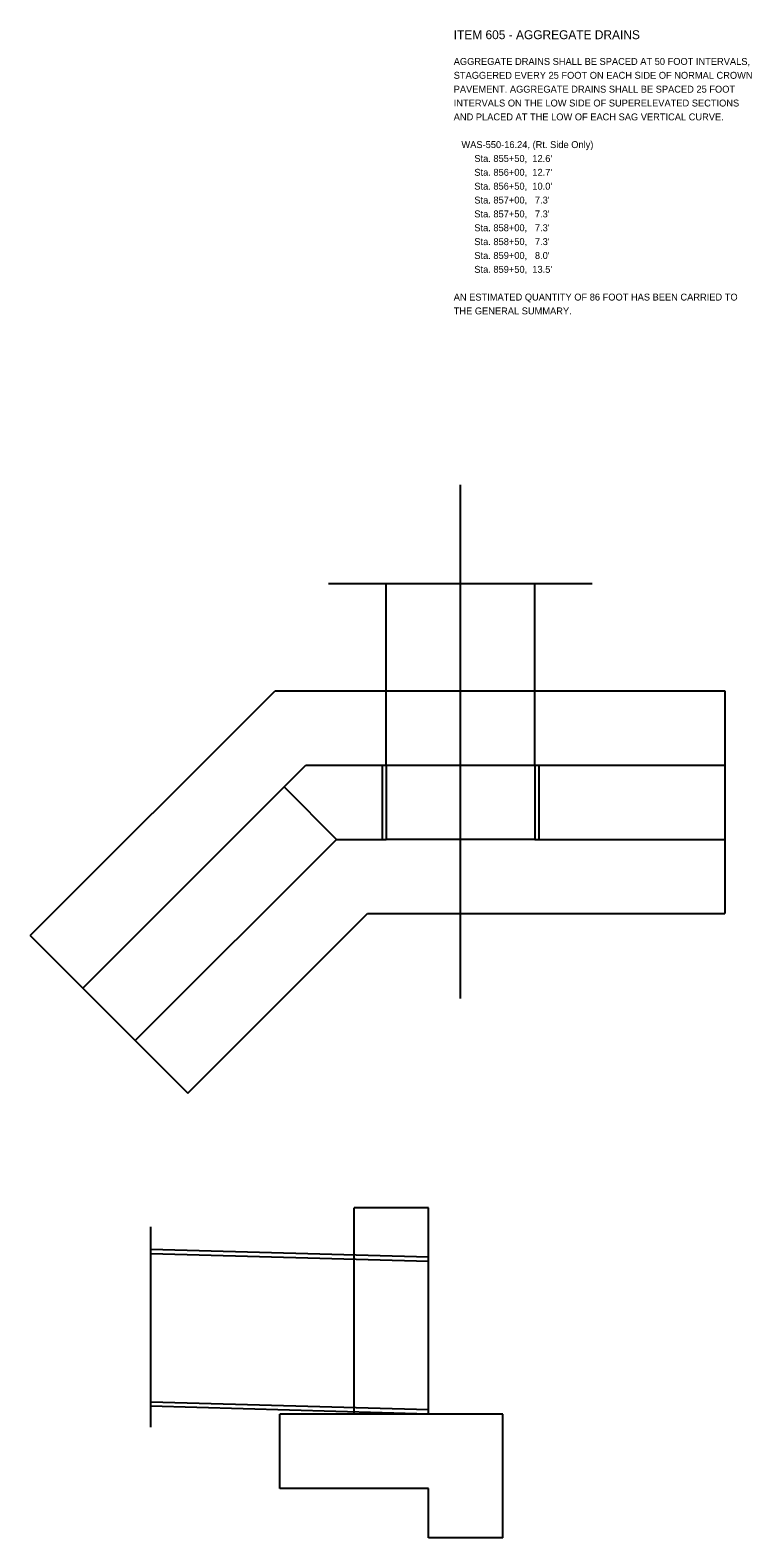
# Model space of a CAD drawing. Extents: x -30 to 76, y -31 to 50.
# Drawn here: x 0.2 to 14.77, y -31.43 to -0.98 of the extents above; entities that cross this region are included whole.
import ezdxf

# ---------------------------------------------------------------- set-up
doc = ezdxf.new("R2010")
doc.units = 0
for name, color, linetype in [('DR_P_Culvert', 7, 'Continuous'), ('DR_P_Headwall', 7, 'Continuous'), ('SH_Text', 7, 'Continuous'), ('XS_P_Headwall', 7, 'Continuous')]:
    doc.layers.add(name, color=color, linetype=linetype)

msp = doc.modelspace()

# ---------------------------------------------------------------- linework, layer by layer
at = {"layer": 'DR_P_Culvert'}
for p, q in [((7.384, -15.824), (7.384, -12.152)), ((10.384, -15.824), (10.384, -12.152)), ((7.301, -15.824), (7.301, -17.324)), ((7.384, -15.824), (7.384, -17.324)), ((10.384, -15.824), (10.384, -17.324)), ((10.467, -15.824), (10.467, -17.324)), ((8.236, -25.851), (2.631, -25.694)), ((8.236, -25.767), (2.633, -25.611)), ((8.236, -28.934), (8.236, -25.767)), ((8.236, -28.934), (2.629, -28.777)), ((8.236, -28.851), (2.631, -28.694))]:
    msp.add_line(p, q, dxfattribs=at)
at = {"layer": 'DR_P_Headwall'}
for p, q in [((0.197, -19.268), (5.141, -14.324)), ((5.141, -14.324), (7.384, -14.324)), ((7.384, -14.324), (10.384, -14.324)), ((10.384, -14.324), (14.217, -14.324)), ((14.217, -14.324), (14.217, -15.824)), ((1.258, -20.329), (5.763, -15.824)), ((5.763, -15.824), (7.384, -15.824)), ((7.384, -15.824), (10.384, -15.824)), ((10.384, -15.824), (14.217, -15.824)), ((14.217, -15.824), (14.217, -17.324)), ((5.323, -16.263), (6.384, -17.324)), ((2.318, -21.389), (6.384, -17.324)), ((6.384, -17.324), (7.384, -17.324)), ((10.384, -17.324), (7.384, -17.324)), ((10.384, -17.324), (14.217, -17.324)), ((14.217, -17.324), (14.217, -18.824)), ((3.379, -22.45), (7.005, -18.824)), ((7.005, -18.824), (14.217, -18.824)), ((0.197, -19.268), (1.258, -20.329)), ((1.258, -20.329), (2.318, -21.389)), ((2.318, -21.389), (3.379, -22.45)), ((8.236, -28.934), (6.736, -28.934))]:
    msp.add_line(p, q, dxfattribs=at)
at = {"layer": 'SH_Text'}
for p, q in [((8.884, -20.538), (8.884, -10.161)), ((6.219, -12.152), (11.54, -12.152))]:
    msp.add_line(p, q, dxfattribs=at)
at = {"layer": 'XS_P_Headwall'}
for p, q in [((6.736, -25.813), (6.736, -24.767)), ((8.236, -24.767), (6.736, -24.767)), ((8.236, -25.767), (8.236, -24.767)), ((2.631, -29.199), (2.631, -25.149)), ((6.736, -28.892), (6.736, -25.813)), ((5.236, -30.434), (5.236, -28.934)), ((6.736, -28.934), (5.236, -28.934)), ((6.736, -28.934), (6.736, -28.892)), ((9.736, -28.934), (8.236, -28.934)), ((9.736, -31.434), (9.736, -28.934)), ((8.236, -30.434), (5.236, -30.434)), ((8.236, -31.434), (8.236, -30.434)), ((9.736, -31.434), (8.236, -31.434))]:
    msp.add_line(p, q, dxfattribs=at)

# ---------------------------------------------------------------- texts
at = {"layer": 'SH_Text'}
for s, height, p in [('ITEM 605 - AGGREGATE DRAINS', 0.18, (8.747, -1.158)), ('AGGREGATE DRAINS SHALL BE SPACED AT 50 FOOT INTERVALS,', 0.14, (8.747, -1.678)), ('STAGGERED EVERY 25 FOOT ON EACH SIDE OF NORMAL CROWN', 0.14, (8.747, -1.958)), ('PAVEMENT. AGGREGATE DRAINS SHALL BE SPACED 25 FOOT', 0.14, (8.747, -2.238)), ('INTERVALS ON THE LOW SIDE OF SUPERELEVATED SECTIONS', 0.14, (8.747, -2.518)), ('AND PLACED AT THE LOW OF EACH SAG VERTICAL CURVE.', 0.14, (8.747, -2.798)), ('   WAS-550-16.24, (Rt. Side Only)', 0.14, (8.747, -3.358)), ("        Sta. 855+50,  12.6'", 0.14, (8.747, -3.638)), ("        Sta. 856+00,  12.7'", 0.14, (8.747, -3.918)), ("        Sta. 856+50,  10.0'", 0.14, (8.747, -4.198)), ("        Sta. 857+00,   7.3'", 0.14, (8.747, -4.478)), ("        Sta. 857+50,   7.3'", 0.14, (8.747, -4.758)), ("        Sta. 858+00,   7.3'", 0.14, (8.747, -5.038)), ("        Sta. 858+50,   7.3'", 0.14, (8.747, -5.318)), ("        Sta. 859+00,   8.0'", 0.14, (8.747, -5.598)), ("        Sta. 859+50,  13.5'", 0.14, (8.747, -5.878)), ('AN ESTIMATED QUANTITY OF 86 FOOT HAS BEEN CARRIED TO', 0.14, (8.747, -6.438)), ('THE GENERAL SUMMARY.', 0.14, (8.747, -6.718))]:
    msp.add_text(s, height=height, dxfattribs=at).set_placement(p)

doc.saveas('drawing.dxf')
